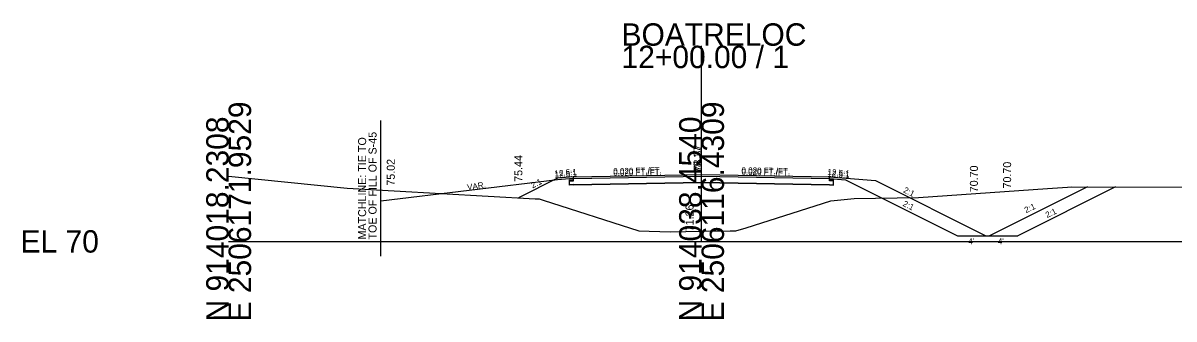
# Model space of a CAD drawing. Extents: x -26 to 403, y -10 to 2549.
# Drawn here: x -25.7 to 118.1, y 990.3 to 1027.3 of the extents above; entities that cross this region are included whole.
import ezdxf

# ---------------------------------------------------------------- set-up
doc = ezdxf.new("R2010")
doc.units = 0
for name, color, linetype in [('RD_GPK_XS_Cell', 7, 'Continuous'), ('RD_Sketch9', 7, 'Continuous'), ('RD_XS_EarthShd', 7, 'Continuous'), ('RD_XS_ExGround', 7, 'Continuous'), ('RD_XS_Pave', 7, 'Continuous'), ('RD_XS_PaveOvlay', 7, 'Continuous'), ('RD_XS_TieSlope', 7, 'Continuous'), ('RD_XS_TX_Elev_EX', 7, 'Continuous'), ('RD_XS_TX_Elev_PR', 7, 'Continuous'), ('RD_XS_TX_ShdSlope', 7, 'Continuous'), ('RD_XS_TX_Slope', 7, 'Continuous')]:
    doc.layers.add(name, color=color, linetype=linetype)

msp = doc.modelspace()

# ---------------------------------------------------------------- linework, layer by layer
at = {"layer": 'RD_GPK_XS_Cell'}
for p, q in [((59.09, 1000), (59.09, 1024.45)), ((0, 1000), (59.09, 1000)), ((59.09, 1000), (259.09, 1000))]:
    msp.add_line(p, q, dxfattribs=at)
at = {"layer": 'RD_Sketch9'}
for p, q in [((43.09, 1008.05), (59.09, 1008.37)), ((59.09, 1008.37), (75.09, 1008.05)), ((41.09, 1007.89), (36.2, 1005.44)), ((43.09, 1008.05), (41.09, 1007.89)), ((42.59, 1007.71), (43.09, 1007.72)), ((42.59, 1007.04), (42.59, 1007.71)), ((43.09, 1007.05), (42.59, 1007.04)), ((43.09, 1007.72), (43.09, 1008.05)), ((43.09, 1007.05), (59.09, 1007.37)), ((59.09, 1007.37), (75.09, 1007.05)), ((75.09, 1007.72), (75.09, 1008.05)), ((75.09, 1008.05), (80.83, 1007.59)), ((75.59, 1007.71), (75.09, 1007.72)), ((75.09, 1007.05), (75.59, 1007.04)), ((75.59, 1007.04), (75.59, 1007.71)), ((80.83, 1007.59), (94.61, 1000.7)), ((110.82, 1006.81), (98.61, 1000.7)), ((94.61, 1000.7), (98.61, 1000.7))]:
    msp.add_line(p, q, dxfattribs=at)
at = {"layer": 'RD_XS_EarthShd'}
for p, q in [((43.09, 1007.85), (41.09, 1007.69)), ((75.09, 1007.85), (77.09, 1007.69))]:
    msp.add_line(p, q, dxfattribs=at)
at = {"layer": 'RD_XS_ExGround'}
for p, q in [((0, 1008.15), (14.8, 1006.66)), ((102.32, 1006.63), (104.8, 1006.77)), ((104.8, 1006.77), (105.35, 1006.82)), ((105.35, 1006.82), (146, 1006.73)), ((14.8, 1006.66), (38.28, 1005.33)), ((38.28, 1005.33), (38.81, 1005.3)), ((38.81, 1005.3), (39.29, 1005.15)), ((75.25, 1005.07), (78.15, 1005.38)), ((78.15, 1005.38), (86.21, 1005.49)), ((86.21, 1005.49), (102.32, 1006.63)), ((39.29, 1005.15), (51.27, 1001.33)), ((64.67, 1001.68), (75.25, 1005.07)), ((51.27, 1001.33), (55.17, 1001.2)), ((55.17, 1001.2), (59.09, 1001.26)), ((59.09, 1001.26), (62.65, 1001.31)), ((62.65, 1001.31), (63.39, 1001.34)), ((63.39, 1001.34), (64.67, 1001.68))]:
    msp.add_line(p, q, dxfattribs=at)
at = {"layer": 'RD_XS_Pave'}
for p, q in [((42.59, 1007.56), (43.09, 1007.57)), ((42.59, 1007.08), (42.59, 1007.56)), ((43.09, 1007.09), (42.59, 1007.08)), ((43.09, 1007.57), (43.09, 1007.85)), ((43.09, 1007.09), (59.09, 1007.41)), ((59.09, 1007.41), (75.09, 1007.09)), ((75.09, 1007.57), (75.09, 1007.85)), ((75.59, 1007.56), (75.09, 1007.57)), ((75.09, 1007.09), (75.59, 1007.08)), ((75.59, 1007.08), (75.59, 1007.56))]:
    msp.add_line(p, q, dxfattribs=at)
at = {"layer": 'RD_XS_PaveOvlay'}
for p, q in [((43.09, 1007.85), (59.09, 1008.17)), ((59.09, 1008.17), (75.09, 1007.85))]:
    msp.add_line(p, q, dxfattribs=at)
at = {"layer": 'RD_XS_TieSlope'}
for p, q in [((19.03, 998.14), (19.03, 1015.09)), ((41.09, 1007.69), (19.03, 1005.02)), ((77.09, 1007.69), (91.07, 1000.7)), ((107.3, 1006.81), (95.07, 1000.7)), ((91.07, 1000.7), (95.07, 1000.7))]:
    msp.add_line(p, q, dxfattribs=at)

# ---------------------------------------------------------------- texts
at = {"layer": 'RD_GPK_XS_Cell'}
for s, p in [('BOATRELOC', (49.09, 1024.45)), ('12+00.00 / 1', (49.09, 1021.65)), ('EL 70', (-26, 998.6))]:
    msp.add_text(s, height=2.8, dxfattribs=at).set_placement(p)
for s, p in [('E 2506171.9529', (2.8, 990)), ('E 2506116.4309', (61.89, 990)), ('N 914018.2308', (0, 990)), ('N 914038.4540', (59.09, 990))]:
    msp.add_text(s, height=2.8, rotation=90, dxfattribs=at).set_placement(p)
at = {"layer": 'RD_Sketch9'}
for s, height, rotation, p in [(' 78.37', 1, 90, (59.09, 1008.37)), (' 78.37', 1, 90, (59.09, 1008.37)), ('75.44', 1, 90, (36.7, 1007.44)), ('70.70', 1, 90, (97.77, 1006.61)), ('12.5:1', 0.75, 4.5739, (40.75, 1008.11)), ('0.020 FT./FT.', 0.75, 1.1458, (48.06, 1008.4)), ('0.020 FT./FT.', 0.75, 358.8542, (64.07, 1008.52)), ('12.5:1', 0.75, 355.4261, (74.79, 1008.32)), ('2:1', 0.75, 26.5651, (37.98, 1006.61)), ('2:1', 0.75, 333.4349, (84.23, 1006.17)), ('2:1', 0.75, 25.4593, (102.27, 1002.91)), ("4'", 0.75, 2.665, (96.13, 999.62))]:
    msp.add_text(s, height=height, rotation=rotation, dxfattribs=at).set_placement(p)
at = {"layer": 'RD_XS_TX_Elev_EX'}
msp.add_text('71.26', height=1, rotation=90, dxfattribs=at).set_placement((58.09, 1001.26))
at = {"layer": 'RD_XS_TX_Elev_PR'}
for s, p in [('MATCHLINE: TIE TO', (17.18, 1000.24)), ('TOE OF FILL OF S-45', (18.48, 1000.24)), (' 78.17', (59.09, 1008.17)), ('75.02', (20.76, 1006.96)), ('70.70', (93.62, 1006.14))]:
    msp.add_text(s, height=1, rotation=90, dxfattribs=at).set_placement(p)
at = {"layer": 'RD_XS_TX_ShdSlope'}
for rotation, p in [(4.5739, (40.75, 1007.91)), (355.4261, (74.79, 1008.12))]:
    msp.add_text('12.5:1', height=0.75, rotation=rotation, dxfattribs=at).set_placement(p)
at = {"layer": 'RD_XS_TX_Slope'}
for s, rotation, p in [('0.020 FT./FT.', 1.1458, (48.06, 1008.2)), ('0.020 FT./FT.', 358.8542, (64.07, 1008.32)), ('VAR.', 8.6548, (29.86, 1006.38)), ('2:1', 333.4349, (84.16, 1004.47)), ('2:1', 25.4593, (99.64, 1003.52)), ("4'", 2.665, (92.44, 999.62))]:
    msp.add_text(s, height=0.75, rotation=rotation, dxfattribs=at).set_placement(p)

doc.saveas('drawing.dxf')
